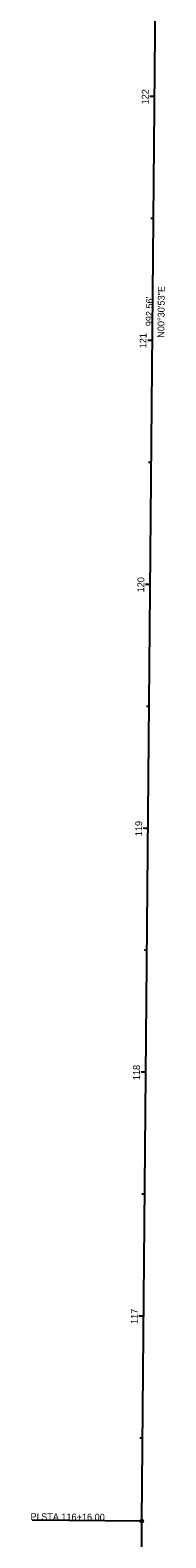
# Model space of a CAD drawing. Extents: x 177110 to 177558, y 286252 to 294117.
# Drawn here: x 177123 to 177178, y 287482 to 288100 of the extents above; entities that cross this region are included whole.
import ezdxf

# ---------------------------------------------------------------- set-up
doc = ezdxf.new("R2010")
doc.units = 0
for name, color, linetype in [('GE_X_Alignment_500_Bearings', 7, 'Continuous'), ('GE_X_Alignment_500_Cardinal_Points', 7, 'Continuous'), ('GE_X_Alignment_500_Distances', 7, 'Continuous'), ('GE_X_Alignment_500_Stations', 7, 'Continuous'), ('RW_X_CL', 7, 'Continuous'), ('RW_X_CL_100_Bearings', 7, 'Continuous'), ('RW_X_CL_100_Cardinal_Points', 7, 'Continuous'), ('RW_X_CL_100_Distances', 7, 'Continuous'), ('RW_X_CL_100_Stations', 7, 'Continuous')]:
    doc.layers.add(name, color=color, linetype=linetype)

msp = doc.modelspace()

# ---------------------------------------------------------------- linework, layer by layer
at = {"layer": 'GE_X_Alignment_500_Cardinal_Points'}
msp.add_line((177168.31, 287489.01), (177123.31, 287489.41), dxfattribs=at)
msp.add_circle((177168.31, 287489.01), 0.6, dxfattribs=at)
at = {"layer": 'GE_X_Alignment_500_Stations'}
for p, q in [((177173.55, 288072.99), (177172.35, 288073)), ((177172.66, 287972.99), (177171.46, 287973)), ((177171.76, 287872.99), (177169.76, 287873.01)), ((177170.86, 287773), (177169.66, 287773.01)), ((177169.96, 287673), (177168.76, 287673.01)), ((177169.06, 287573.01), (177167.86, 287573.02))]:
    msp.add_line(p, q, dxfattribs=at)
at = {"layer": 'RW_X_CL'}
for p, q in [((177168.31, 287489.01), (177177.22, 288481.53)), ((177157.11, 286252.3), (177168.31, 287489.01))]:
    msp.add_line(p, q, dxfattribs=at)
at = {"layer": 'RW_X_CL_100_Cardinal_Points'}
msp.add_line((177168.31, 287489.01), (177123.31, 287489.41), dxfattribs=at)
msp.add_circle((177168.31, 287489.01), 0.6, dxfattribs=at)
at = {"layer": 'RW_X_CL_100_Stations'}
for p, q in [((177173.55, 288072.99), (177171.55, 288073)), ((177173.1, 288022.99), (177171.9, 288023)), ((177172.66, 287972.99), (177170.66, 287973.01)), ((177172.21, 287922.99), (177171.01, 287923)), ((177171.76, 287872.99), (177169.76, 287873.01)), ((177171.31, 287823), (177170.11, 287823.01)), ((177170.86, 287773), (177168.86, 287773.02)), ((177170.41, 287723), (177169.21, 287723.01)), ((177169.96, 287673), (177167.96, 287673.02)), ((177169.51, 287623), (177168.31, 287623.01)), ((177169.06, 287573.01), (177167.06, 287573.02)), ((177168.61, 287523.01), (177167.41, 287523.02))]:
    msp.add_line(p, q, dxfattribs=at)

# ---------------------------------------------------------------- texts
at = {"layer": 'GE_X_Alignment_500_Bearings'}
msp.add_text('N00°30\'53"E', height=2.8, rotation=89.48526, dxfattribs=at).set_placement((177177.47, 287974.11))
at = {"layer": 'GE_X_Alignment_500_Cardinal_Points'}
for s, p in [('PI', (177122.61, 287489.46)), (' STA. ', (177125.93, 287489.43)), ('116+16.00', (177135.25, 287489.34))]:
    msp.add_text(s, height=2.8, rotation=359.48526, dxfattribs=at).set_placement(p)
at = {"layer": 'GE_X_Alignment_500_Distances'}
msp.add_text("992.56'", height=2.8, rotation=89.48526, dxfattribs=at).set_placement((177172.67, 287978.83))
at = {"layer": 'GE_X_Alignment_500_Stations'}
msp.add_text('120', height=2.8, rotation=89.48526, dxfattribs=at).set_placement((177169.23, 287869.75))
at = {"layer": 'RW_X_CL_100_Bearings'}
msp.add_text('N00°30\'53"E', height=2.8, rotation=89.48526, dxfattribs=at).set_placement((177177.47, 287974.11))
at = {"layer": 'RW_X_CL_100_Cardinal_Points'}
for s, p in [('PI', (177122.61, 287489.46)), (' STA. ', (177125.93, 287489.43)), ('116+16.00', (177135.25, 287489.34))]:
    msp.add_text(s, height=2.8, rotation=359.48526, dxfattribs=at).set_placement(p)
at = {"layer": 'RW_X_CL_100_Distances'}
msp.add_text("992.56'", height=2.8, rotation=89.48526, dxfattribs=at).set_placement((177172.67, 287978.83))
at = {"layer": 'RW_X_CL_100_Stations'}
for s, p in [('122', (177171.02, 288069.8)), ('121', (177170.13, 287969.79)), ('120', (177169.23, 287869.75)), ('119', (177168.33, 287769.79)), ('118', (177167.43, 287669.77)), ('117', (177166.53, 287569.79))]:
    msp.add_text(s, height=2.8, rotation=89.48526, dxfattribs=at).set_placement(p)

doc.saveas('drawing.dxf')
